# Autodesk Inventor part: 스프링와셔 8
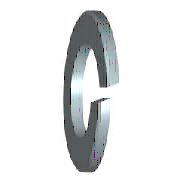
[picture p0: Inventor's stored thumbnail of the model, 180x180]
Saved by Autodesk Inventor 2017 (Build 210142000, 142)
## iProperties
IsCustomPart: 1
Created: 2012-02
Part Number: 스프링와셔 8
Material: 강철, 연강
Description: 스프링 잠금 와셔
Document SubType Name: Modeling
Standard: KS B 1324
Designer: mduedu
Standards Organization: KS
Language: ko-KR
Size Designation: 번호 3 - 8
Categories: <MemberInstance><Categories><Category DisplayName="조임쇠" InternalName="e4da775c-781d-43d5-af7c-5136215cf5a6" Mnemonic="FSTN"><Category DisplayName="와셔" InternalN
Density: 7.86 g/cm^3
Mass: 2.27751 g
Surface Area: 4.25113 cm^2
Volume: 0.289759 cm^3
Appearance: 파란색 - 벽 페인트 - 광택
Author: mduedu
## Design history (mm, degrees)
sketch "스케치1"
  geometry: C1 r 7.4 at (0, 0); C2 r 4.1 at (0, 0); 1 further point
  constraints: 2 centre point, 2 coincident
  dimensions: "d0" = 8.2 diameter of C2 (= SD1); "d1" = 14.8 diameter of C1 (= SD2)
extrude "본체" new body sketch "스케치1" distance "d2" = 2.5 (= SD); taper "d3" = 0 deg
sketch "스케치2"
  geometry: L1 (0, -4.1)-(0, 4.1) reference; L2 (2.5, 7.4)-(2.5, -7.4) reference; L3 (-1.2, 0)-(7.2, 0) reference; L4 (0, -0.5)-(2.5, 0.41); L5 (0, 0.5)-(2.5, 1.41)
  constraints: 4 end point, 4 point on line, 1 parallel
  dimensions: "d4" = 0.5 distance from line of L3 L4.start (= 0.2 x SD); "d5" = 0.5 distance from line of L3 L5.start (= 0.2 x SD); "d6" = 70 deg angle of L2 L4 (= FAWI)
extrude "절단부" cut sketch "스케치2" stored distance "d7" = 2.5 (= SD); taper "d8" = 0 deg
workaxis "Work Axis1"
workplane "Work Plane1"
body "Solid1"
other parameters: "SD1" = 8.2 [user parameter; used in 1 equation term], "SD2" = 14.8 [user parameter; used in 1 equation term], "SD" = 2.5 [user parameter; used in 4 equation terms], "FAWI" = 70 deg [user parameter; used in 1 equation term], "d9" = 0, "d10" = 0, "d11" = 0, "d12" = 0, "SDI" = 3.3 [user parameter], "NND" = 8 [user parameter]
